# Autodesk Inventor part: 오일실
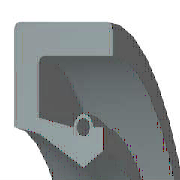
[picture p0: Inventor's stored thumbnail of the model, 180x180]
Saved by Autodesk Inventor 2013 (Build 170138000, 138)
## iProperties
IsCustomPart: 1
Created: 2015-12
Part Number: 오일실
Material: 일반
Description: 오일-실
Document SubType Name: Modeling
Standard: KS B 2804
Designer: mdu
Standards Organization: KS
Language: ko-KR
Size Designation: S - 15 30 7
Categories: <MemberInstance><Categories><Category DisplayName="샤프트 부품" InternalName="7f7aeb1f-a693-4053-b835-cee3144e0d98" Mnemonic="SHFT"><Category DisplayName="실링" Intern
Density: 1 g/cm^3
Mass: 1.76736 g
Surface Area: 26.6454 cm^2
Volume: 1.76736 cm^3
Author: mdu
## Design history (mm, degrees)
revolve "본체" stored, may be unused: angle "d17" = 90 deg
revolve "스프링1" stored, may be unused: angle "d18" = 90 deg
body "Solid1"
sketch "스케치1"
  geometry: L1 (0, 15)-(7, 15); L2 (7, 15)-(7, 13.75); L3 (7, 13.75)-(1.75, 13.75); L4 (0, 15)-(0, 9.6); L5 (0, 9.6)-(1.75, 9.25); L6 (1.75, 9.25)-(4.9, 7.5); L7 (4.9, 7.5)-(0, 7.5); L8 (6.3, 8.375)-(6.3, 9.6); L9 (0, 0)-(9.586, 0) reference; L10 (4.9, 7.5)-(6.3, 8.375); L11 (0, 18)-(0, -3) reference; L12 (-1.917, 0)-(11.503, 0) reference; L13 (4.2, 9.6)-(1.75, 10.09); L14 (1.75, 10.09)-(1.75, 13.75); L15 (6.3, 9.6)-(5.6, 9.6); C1 r 0.455 at (4.9, 9.6); A1 r 0.7 centre (4.9, 9.6) between (5.6, 9.6) and (4.2, 9.6)
  constraints: 26 end point, 5 horizontal alignment, 4 perpendicular, 2 centre point, 2 collinear, 2 horizontal, 2 parallel, 2 point on circle, 2 point on line, 2 vertical alignment, 1 coincident
  dimensions: "d0" = 30 diameter of L1 L9 (= SD2); "d1" = 16.75 diameter of L8.start L9 (= ABDM); "d2" = 1.25 distance of L1.end L2.end (computed from SD); "d3" = 0.91 diameter of C1 (= SPDI); "d4" = 1.4 diameter of A1 (= SPDA); "d5" = 15 diameter of L6.end L9 (= NND); "d6" = 18.5 diameter of L5.end L9 (= TKDM); "d7" = 19.2 diameter of L4.end L9 (= HLDM); "d8" = 4.9 distance from line of C1.centre L4 (= SPDST); "d9" = 6.3 distance between parallel lines of L8 L4 (= SDI); "d10" = 7 distance between parallel lines of L2 L4 (= SWDT); "d12" = 1.75 distance between parallel lines of L14 L4 (= SD)
fillet "모깎기1" dims "d11" = 0.3 (= RR)
other parameters: "SD2" = 30 [user parameter; used in 1 equation term], "SWDT" = 7 [user parameter; used in 1 equation term], "RR" = 0.3 [user parameter; used in 1 equation term], "SD" = 1.75 [user parameter; used in 2 equation terms], "NND" = 15 [user parameter; used in 1 equation term], "SPDA" = 1.4 [user parameter; used in 1 equation term], "SPDI" = 0.91 [user parameter; used in 1 equation term], "TKDM" = 18.5 [user parameter; used in 1 equation term], "HLDM" = 19.2 [user parameter; used in 1 equation term], "ABDM" = 16.75 [user parameter; used in 1 equation term], "SDI" = 6.3 [user parameter; used in 1 equation term], "SPDST" = 4.9 [user parameter; used in 1 equation term], "d13" = 0, "d14" = 0, "d15" = 0, "LAB" = 0.35 [user parameter]
